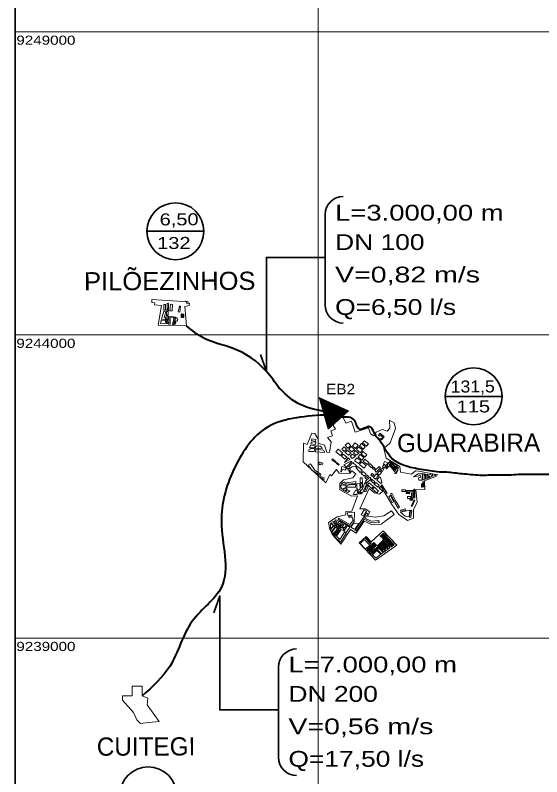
# Model space of a CAD drawing. Extents: x 0 to 1772, y 0 to 1188.
# Drawn here: x 487.8 to 598.6, y 161 to 321.1 of the extents above; entities that cross this region are included whole.
import ezdxf
from ezdxf.enums import TextEntityAlignment as Align

# ---------------------------------------------------------------- set-up
doc = ezdxf.new("R2010")
doc.units = 0
doc.header["$LTSCALE"] = 1.3
doc.linetypes.add('DOT_DASHED', pattern=[7.7, 5, -1.2, 0.3, -1.2])
doc.linetypes.add('LONG_DASHED', pattern=[7.5, 6, -1.5])
for name, color, linetype, lineweight in [('1', 7, 'DOT_DASHED', 13), ('4', 7, 'Continuous', 13), ('5', 7, 'LONG_DASHED', 25), ('6', 7, 'Continuous', 40), ('63', 7, 'Continuous', 25), ('8', 7, 'Continuous', 35), ('9', 7, 'Continuous', 40)]:
    doc.layers.add(name, color=color, linetype=linetype, lineweight=lineweight)

msp = doc.modelspace()

# ---------------------------------------------------------------- linework, layer by layer
at = {"layer": '1', "linetype": 'Continuous'}
for p, q in [((563.262, 232.663), (563.749, 233.457)), ((553.151, 222.824), (553.985, 224.573)), ((555.553, 213.259), (555.221, 213.471))]:
    msp.add_line(p, q, dxfattribs=at)
for points in [[(523.656, 261.085), (524.279, 260.753), (523.858, 260.69), (523.892, 260.461), (524.458, 260.546), (524.38, 260.047), (523.476, 259.846), (523.848, 255.792), (517.883, 255.948), (518.577, 260.092), (517.126, 260.187), (517.157, 260.657), (516.544, 260.697), (516.584, 261.31), (524.165, 260.814)], [(563.262, 232.663), (562.545, 233.076), (562.126, 234.357), (559.295, 233.433), (558.546, 235.728), (557.358, 235.34), (555.556, 239.053), (554.403, 238.494), (554.722, 237.837), (553.371, 237.181), (555.216, 234.062), (554.179, 233.705), (554.536, 232.668), (553.499, 232.311), (554.274, 231.406), (553.905, 229.172), (553.336, 229.266), (552.907, 230.716), (551.581, 231.155), (551.578, 231.995), (550.846, 233.164), (550.183, 233.251), (549.263, 230.838), (548.474, 231.139), (548.412, 227.232), (553.151, 222.824)], [(576.701, 224.479), (576.701, 224.479), (572.667, 225.222), (572.046, 225.336), (571.199, 224.614), (568.899, 225.022), (568.707, 226.266), (565.838, 227.955), (565.342, 229.991), (566.658, 231.24), (567.817, 234.223), (567.55, 235.392), (566.531, 235.955), (566.611, 234.258), (566.085, 233.652), (565.029, 233.989), (563.749, 233.457)], [(553.985, 224.573), (554.384, 224.265), (555.429, 225.615), (555.994, 224.822), (558.203, 224.763), (558.621, 225.317), (559.439, 224.699), (558.822, 223.881), (556.882, 223.41), (556.089, 222.634), (556.137, 221.307), (558.659, 220.011), (559.829, 220.036), (558.602, 216.871), (557.343, 216.779), (557.393, 216.095), (555.554, 215.637), (553.751, 214.454), (554.014, 212.962), (554.387, 212.123), (554.933, 211.445), (555.991, 210.318), (556.349, 209.938), (558.355, 212.972), (559.528, 212.196), (561.216, 214.749), (562.788, 214.025), (564.812, 214.12), (567.547, 216.166), (566.976, 216.929), (565.367, 215.87), (563.588, 215.586), (561.896, 215.793), (562.394, 216.674), (561.446, 217.351), (560.312, 217.336), (562.301, 221.63), (563.372, 220.709), (564.43, 220.422), (565.284, 221.16), (567.017, 218.225), (568.537, 216.147), (570.363, 214.89), (571.591, 215.342), (571.628, 217.105), (572.364, 218.758), (572.105, 221.347), (573.964, 221.366), (573.944, 223.225), (576.472, 224.2)], [(555.221, 213.471), (554.417, 212.355), (554.678, 212.167), (555.382, 212.861), (555.553, 213.259)]]:
    msp.add_lwpolyline(points, dxfattribs=at)
for points in [[(519.064, 259.089), (519.06, 260.291), (519.42, 260.293), (519.424, 259.09)], [(520.092, 259.451), (520.089, 260.493), (519.779, 260.492), (519.782, 259.45)], [(520.342, 258.956), (520.461, 260.345), (520.93, 260.305), (520.81, 258.916)], [(522.103, 258.751), (522.384, 259.954), (522.608, 259.902), (522.463, 258.702)], [(518.574, 257.19), (519.077, 258.878), (519.507, 258.75), (519.159, 257.584), (519.398, 257.513), (519.442, 257.081)], [(519.578, 257.144), (519.576, 257.937), (519.923, 257.938), (519.925, 257.145)], [(519.65, 258.136), (519.648, 258.793), (519.97, 258.794), (519.972, 258.137)], [(519.722, 258.979), (519.721, 259.202), (520.068, 259.203), (520.069, 258.98)], [(520.152, 256.104), (520.146, 257.852), (521.089, 257.694), (521.053, 257.477), (520.437, 257.58), (520.424, 256.117)], [(522.702, 257.55), (522.699, 258.294), (522.972, 258.294), (522.974, 257.55)], [(523.123, 257.526), (523.121, 258.27), (523.319, 258.271), (523.322, 257.527)], [(518.427, 256.508), (518.55, 256.967), (519.443, 256.895), (519.386, 256.196), (518.372, 256.278)], [(519.643, 256.276), (519.641, 256.908), (519.889, 256.909), (519.891, 256.277)], [(520.908, 256.106), (521.288, 257.645), (521.51, 257.59), (521.13, 256.051)], [(521.268, 256.07), (521.44, 256.641), (521.573, 256.6), (521.434, 256.137)], [(521.414, 256.839), (521.635, 257.571), (521.861, 257.503), (521.793, 257.277), (522.019, 257.209), (521.898, 256.807), (521.662, 256.878), (521.591, 256.643)], [(565.44, 232.496), (564.557, 233.215), (564.243, 232.829), (564.516, 232.607), (564.738, 232.88), (565.134, 232.322), (564.744, 232.045), (564.507, 232.133), (564.615, 231.906), (564.868, 231.813)], [(550.787, 230.171), (549.75, 230.168), (549.948, 230.707), (550.886, 230.61)], [(549.972, 230.995), (550.146, 231.446), (551.034, 231.323), (550.971, 230.866)], [(551.008, 231.473), (550.145, 231.671), (550.238, 232.075), (551.082, 231.882)], [(552.413, 229.951), (551.012, 230.11), (551.065, 230.578), (551.994, 230.473), (552.324, 230.239)], [(557.771, 230.075), (557.252, 230.697), (557.875, 231.216), (558.393, 230.594)], [(559.397, 230.004), (558.757, 230.595), (559.349, 231.235), (559.989, 230.644)], [(561.07, 229.887), (560.262, 230.554), (560.66, 231.035), (561.467, 230.368)], [(561.721, 230.513), (560.899, 231.18), (561.282, 231.653), (562.105, 230.986)], [(550.74, 229.358), (549.565, 229.354), (549.563, 229.73), (550.063, 230.044), (550.825, 229.959)], [(551.015, 229.309), (552.94, 229.152), (552.676, 229.689), (551.025, 229.872)], [(556.21, 228.549), (555.296, 229.322), (555.754, 229.863), (556.668, 229.09)], [(557.013, 229.373), (556.495, 229.873), (556.995, 230.392), (557.514, 229.891)], [(557.912, 228.599), (557.257, 229.176), (557.709, 229.689), (558.439, 229.047)], [(558.655, 229.317), (557.984, 229.908), (558.459, 230.446), (559.193, 229.799)], [(559.569, 228.589), (558.959, 229.12), (559.36, 229.579), (560.074, 228.957)], [(560.418, 229.124), (559.58, 229.791), (560.042, 230.371), (560.88, 229.704)], [(561.364, 228.184), (560.571, 228.912), (561.024, 229.405), (561.817, 228.677)], [(555.296, 227.269), (554.544, 227.83), (554.414, 227.656), (555.165, 227.095)], [(557.17, 227.745), (556.438, 228.397), (556.824, 228.83), (557.555, 228.177)], [(558.615, 227.278), (557.54, 226.072), (556.957, 226.592), (558.417, 227.353)], [(558.234, 227.687), (557.838, 228.021), (557.059, 227.096)], [(558.72, 227.917), (558.262, 228.387), (558.733, 228.845), (559.372, 228.436)], [(560, 226.871), (559.223, 227.416), (559.674, 228.058), (560.567, 227.431)], [(560.727, 227.588), (559.935, 228.271), (560.374, 228.781), (561.167, 228.099)], [(561.855, 226.633), (560.986, 227.345), (561.348, 227.787), (562.217, 227.074)], [(568.282, 225.818), (567.429, 226.577), (566.53, 227.2), (566.645, 227.366), (567.504, 226.771), (567.791, 226.737), (568.133, 226.409), (568.054, 226.326), (568.423, 225.971)], [(552.029, 224.369), (550.201, 225.427), (549.473, 226.526), (549.913, 226.817), (550.823, 225.443), (552.141, 224.632)], [(551.923, 226.608), (551.597, 226.845), (551.834, 227.171), (552.522, 226.936), (552.436, 226.684), (552.184, 226.77)], [(555.997, 226.671), (555.496, 227.107), (555.335, 226.923), (555.837, 226.486)], [(556.326, 225.125), (556.536, 226.252), (558.255, 225.709), (558.257, 225.07), (558.075, 225.07), (558.073, 225.48), (557.83, 225.48), (557.829, 225.723), (557.313, 225.721), (557.313, 225.493), (556.629, 225.674), (556.488, 225.14)], [(558.01, 226.195), (558.874, 227.065), (559.607, 226.338), (559.409, 226.139), (558.998, 226.244), (558.679, 226.137), (558.365, 225.931), (558.244, 225.852), (558.15, 225.885)], [(560.779, 225.443), (559.804, 226.246), (559.534, 225.919), (560.4, 224.97)], [(561.188, 225.901), (560.213, 226.643), (560.64, 227.203), (561.615, 226.46)], [(562.799, 225.951), (562.159, 226.543), (562.432, 226.838), (563.072, 226.247)], [(563.271, 225.572), (562.997, 225.815), (563.24, 226.089), (563.514, 225.846)], [(563.744, 225.071), (563.47, 225.36), (564.389, 226.235), (564.664, 225.947)], [(565.051, 225.151), (564.579, 225.515), (565.079, 225.866), (565.26, 225.609)], [(565.422, 225.889), (565.046, 226.184), (565.34, 226.559), (565.795, 226.391)], [(565.862, 226.538), (565.306, 226.719), (565.486, 227.275), (566.282, 227.018)], [(566.295, 226.097), (565.887, 225.755), (565.782, 225.88), (566.033, 226.278)], [(568.055, 225.806), (567.236, 226.565), (566.451, 227.097), (566.006, 226.44), (566.874, 226.03), (567.705, 225.101), (567.841, 225.419), (566.486, 226.574), (566.618, 226.728), (567.92, 225.617)], [(552.745, 223.458), (552.118, 223.931), (552.117, 224.144), (552.793, 223.858)], [(561.223, 224.196), (560.614, 224.742), (561.005, 225.179), (561.614, 224.633)], [(561.605, 223.665), (561.391, 223.923), (561.939, 224.376), (562.153, 224.118)], [(563.002, 224.141), (562.621, 224.414), (562.894, 224.794), (563.275, 224.522)], [(563.627, 223.58), (563.185, 223.913), (563.748, 224.659), (564.268, 224.267)], [(564.724, 222.685), (563.871, 223.352), (564.442, 224.083), (564.667, 223.907), (564.951, 222.96)], [(564.369, 224.434), (563.988, 224.783), (564.452, 225.29), (564.839, 224.936)], [(567.968, 224.727), (567.706, 224.726), (567.706, 224.874), (567.854, 224.874), (568.215, 225.614), (568.365, 225.54)], [(573.424, 223.349), (572.688, 223.346), (572.687, 223.877), (573.174, 223.964), (573.104, 224.356), (572.358, 224.222), (571.612, 224.089), (572.573, 224.716), (573.471, 224.676)], [(573.577, 223.382), (573.952, 223.544), (573.949, 224.68), (573.555, 224.679)], [(575.07, 223.922), (575.476, 224.12), (575.278, 224.526), (574.137, 224.654), (574.154, 223.565), (574.9, 223.882), (574.835, 224.036), (574.412, 223.856), (574.4, 224.418), (574.609, 224.423), (574.613, 224.214), (575.004, 224.222)], [(575.646, 224.186), (575.514, 224.592), (576.641, 224.504)], [(557.271, 222.422), (556.458, 222.557), (556.602, 222.716), (556.816, 222.866), (557, 222.914), (557.183, 222.961)], [(559.48, 222.656), (559.479, 223.112), (557.455, 222.817), (557.501, 222.502)], [(560.029, 221.232), (559.65, 221.632), (559.681, 222.556), (560.281, 222.68), (560.362, 221.534)], [(561.727, 222.551), (561.381, 222.862), (560.84, 221.524), (560.308, 220.988), (560.865, 220.622)], [(560.892, 222.883), (560.414, 222.881), (560.411, 223.817), (560.834, 223.818)], [(560.528, 221.757), (560.526, 222.625), (560.882, 222.627), (560.883, 222.014)], [(561.805, 222.768), (561.485, 223.117), (562.406, 223.962), (562.68, 223.664)], [(562.797, 221.629), (561.898, 222.418), (562.242, 222.811), (563.164, 222.002)], [(563.189, 222.726), (562.625, 223.196), (562.887, 223.511), (563.451, 223.041)], [(564.088, 221.922), (563.356, 222.529), (563.662, 222.898), (564.394, 222.291)], [(573.451, 221.922), (573.449, 222.618), (573.278, 222.617), (573.28, 221.922)], [(573.778, 221.989), (573.775, 223.013), (573.592, 223.012), (573.595, 221.988)], [(557.465, 221.875), (557.305, 222.26), (556.424, 222.355), (556.339, 222.15), (556.335, 221.953), (556.396, 221.743), (556.55, 221.559), (556.625, 221.47)], [(557.405, 221.695), (556.709, 221.376), (556.872, 221.188), (557.082, 221.09), (557.173, 221.048), (557.628, 221.503)], [(557.795, 220.736), (557.283, 220.99), (557.649, 221.325), (558.183, 221.126)], [(559.416, 221.898), (557.592, 221.893), (557.59, 222.26), (558.435, 222.43), (559.503, 222.433)], [(559.776, 220.341), (558.897, 220.338), (559.495, 221.353), (559.844, 221.148)], [(560.654, 220.488), (559.998, 220.486), (559.997, 220.943)], [(562.085, 222.007), (561.761, 222.284), (561.265, 220.98), (561.546, 220.873)], [(563.01, 221.463), (563.894, 220.674), (564.25, 221.073), (563.366, 221.861)], [(564.956, 221.164), (564.347, 221.725), (564.635, 222.039), (565.245, 221.477)], [(564.913, 221.218), (564.356, 221.693), (564.68, 222.073), (565.255, 221.582)], [(564.786, 222.183), (564.967, 222.366), (566.061, 220.653), (565.887, 220.541), (565.48, 221.39)], [(569.18, 220.965), (569.941, 220.967), (569.94, 221.308), (569.179, 221.306)], [(570.124, 220.941), (570.124, 221.217), (571.552, 221.221), (571.553, 220.946)], [(571.872, 219.634), (571.866, 221.498), (571.669, 221.497), (571.675, 219.634)], [(567.09, 218.662), (566.418, 219.959), (566.761, 220.137), (567.433, 218.84)], [(567.574, 218.952), (566.744, 220.485), (567.011, 220.63), (567.841, 219.097)], [(570.086, 220.758), (570.846, 220.76), (570.846, 220.589), (570.086, 220.587)], [(570.312, 219.485), (570.968, 219.487), (570.966, 219.894), (570.311, 219.892)], [(571.44, 219.318), (570.863, 219.316), (570.864, 219.133), (571.441, 219.134)], [(571.479, 219.502), (571.475, 220.722), (571.147, 220.721), (571.151, 219.501)], [(568.378, 217.498), (567.667, 218.69), (567.927, 218.846), (568.639, 217.654)], [(571.3, 217.835), (571.873, 219.188), (571.711, 219.257), (571.138, 217.903)], [(558.224, 214.049), (555.877, 215.407), (555.724, 215.142), (558.366, 213.613), (559.096, 214.529), (559.183, 216.609), (557.727, 216.486), (557.772, 215.951), (558.612, 216.022), (558.63, 215.815), (557.987, 215.76), (558.009, 215.506), (558.682, 215.563), (558.936, 214.873)], [(561.065, 215.78), (561.736, 216.856), (561.256, 217.156), (560.584, 216.081)], [(561.542, 215.53), (562.003, 216.326), (561.704, 216.499), (561.243, 215.703)], [(570.664, 215.655), (569.825, 215.81), (568.892, 216.634), (570.804, 217.046)], [(568.957, 216.818), (569.992, 217.057), (569.93, 217.325), (568.895, 217.086)], [(570.782, 215.616), (570.949, 216.994), (571.233, 216.96), (571.067, 215.581)], [(554.663, 214.105), (554.239, 214.395), (554.675, 214.688), (554.968, 214.252)], [(555.443, 214.611), (554.918, 214.609), (555.296, 215.008), (555.534, 214.982)], [(555.974, 214.069), (556.277, 214.587), (555.942, 214.782), (555.639, 214.265)], [(556.398, 213.792), (556.146, 213.977), (556.557, 214.537), (556.809, 214.352)], [(559.538, 212.662), (561.225, 215.131), (562.418, 214.512), (563.232, 214.408), (564.225, 214.59), (564.247, 214.466), (564.371, 214.489), (564.302, 214.866), (562.706, 214.708), (561.075, 215.497), (559.275, 212.754)], [(554.149, 213.375), (554.147, 214.223), (554.783, 213.814), (554.19, 213.163)], [(555.089, 213.576), (554.837, 213.734), (554.164, 212.924), (554.364, 212.514)], [(555.911, 213.062), (555.672, 213.26), (555.501, 212.796), (554.71, 211.919), (554.923, 211.726)], [(555.154, 213.815), (554.955, 214), (555.319, 214.391), (555.518, 214.206)], [(556.21, 210.32), (557.435, 212.192), (557.063, 212.435), (556.073, 210.923), (555.425, 211.616), (556.256, 212.785), (556.087, 212.904), (555.06, 211.458)], [(555.63, 214.068), (555.34, 213.656), (555.603, 213.471), (555.913, 213.912)], [(556.003, 213.234), (555.791, 213.406), (556.12, 213.813), (556.332, 213.642)], [(556.215, 213.089), (556.772, 212.746), (557.015, 213.142), (556.459, 213.485)], [(556.61, 213.647), (556.982, 213.317), (557.494, 213.893), (557.122, 214.223)], [(556.958, 212.654), (557.448, 212.338), (558.196, 213.497), (557.706, 213.814)], [(558.981, 213.097), (558.438, 213.454), (559.023, 214.348), (560.09, 214.227), (559.273, 213.032)], [(563.602, 206.56), (560.185, 210.176), (561.633, 211.544), (562.728, 210.386), (565.215, 212.736), (568.096, 209.687)], [(562.573, 210.01), (561.41, 211.158), (561.557, 211.308), (562.721, 210.159)], [(564.593, 211.585), (565.267, 212.22), (565.427, 212.05), (564.753, 211.415)], [(564.91, 211.283), (565.555, 211.976), (565.71, 211.831), (565.065, 211.139)], [(565.141, 211.054), (565.8, 211.703), (565.942, 211.558), (565.283, 210.909)], [(565.414, 210.868), (566.016, 211.431), (566.142, 211.296), (565.54, 210.734)], [(561.507, 208.836), (560.352, 210.066), (561.249, 210.908), (562.404, 209.678)], [(563.161, 209.012), (562.575, 209.596), (562.727, 209.749), (563.313, 209.165)], [(563.394, 209.265), (562.826, 209.848), (562.967, 209.986), (563.536, 209.403)], [(563.536, 209.403), (562.967, 209.986), (563.109, 210.124), (563.677, 209.541)], [(563.677, 209.541), (563.109, 210.124), (563.251, 210.263), (563.819, 209.679)], [(565.368, 210.585), (564.122, 209.402), (563.993, 209.537), (565.24, 210.72)], [(564.365, 209.214), (565.576, 210.361), (565.431, 210.513), (564.221, 209.366)], [(566.255, 208.859), (565.824, 208.552), (564.886, 209.512), (565.032, 209.655), (565.741, 208.929), (565.837, 209.023), (565.125, 209.753), (565.228, 209.854)], [(566.649, 209.239), (566.308, 208.949), (565.307, 209.991), (565.436, 210.115), (566.205, 209.315), (566.318, 209.424), (565.593, 210.178), (565.697, 210.277)], [(565.633, 210.624), (566.235, 211.187), (566.361, 211.053), (565.759, 210.49)], [(565.892, 210.409), (566.494, 210.972), (566.62, 210.838), (566.018, 210.275)], [(566.109, 210.136), (566.711, 210.699), (566.836, 210.565), (566.234, 210.002)], [(566.368, 209.893), (566.97, 210.455), (567.096, 210.321), (566.494, 209.758)], [(566.585, 209.634), (567.187, 210.197), (567.312, 210.063), (566.71, 209.5)], [(566.801, 209.39), (567.403, 209.953), (567.528, 209.819), (566.926, 209.256)], [(562.796, 207.832), (561.83, 208.819), (561.995, 208.98), (562.96, 207.993)], [(563.047, 208.085), (562.073, 209.072), (562.204, 209.202), (563.178, 208.214)], [(562.964, 208.741), (562.323, 209.361), (562.478, 209.52), (563.118, 208.901)], [(564.702, 207.783), (563.643, 206.97), (562.958, 207.634), (563.896, 208.602)], [(563.274, 208.421), (564.144, 209.198), (564.022, 209.335), (563.152, 208.558)], [(563.397, 208.284), (564.267, 209.06), (564.144, 209.198), (563.274, 208.421)], [(565.223, 208.145), (564.837, 207.865), (563.998, 208.691), (564.337, 209.035)], [(565.698, 208.435), (565.33, 208.217), (564.455, 209.106), (564.61, 209.258), (565.237, 208.621), (565.353, 208.734), (564.74, 209.356), (564.815, 209.431)], [(514.511, 178.013), (514.511, 180.074), (512.45, 180.074), (512.45, 178.013), (510.389, 178.013), (510.389, 177.123), (512.706, 174.505), (513.37, 172.993), (514.183, 172.218), (515.955, 172.403), (518.127, 172.629), (515.549, 176.165), (515.696, 177.566)]]:
    msp.add_lwpolyline(points, close=True, dxfattribs=at)
at = {"layer": '4'}
for p, q in [((551.784, 240.661), (551.813, 240.69)), ((551.809, 240.573), (551.891, 240.654)), ((551.834, 240.485), (551.968, 240.619)), ((551.859, 240.397), (552.046, 240.583)), ((551.884, 240.309), (552.123, 240.547)), ((551.909, 240.22), (552.201, 240.512)), ((551.934, 240.132), (552.278, 240.476)), ((551.959, 240.044), (552.356, 240.441)), ((551.984, 239.956), (552.433, 240.405)), ((552.009, 239.868), (552.511, 240.37)), ((552.034, 239.78), (552.588, 240.334)), ((552.059, 239.692), (552.666, 240.298)), ((552.084, 239.603), (552.743, 240.263)), ((552.109, 239.515), (552.821, 240.227)), ((552.134, 239.427), (552.899, 240.192)), ((552.159, 239.339), (552.976, 240.156)), ((552.184, 239.251), (553.054, 240.12)), ((552.209, 239.163), (553.131, 240.085)), ((552.234, 239.075), (553.209, 240.049)), ((552.259, 238.986), (553.286, 240.014)), ((552.284, 238.898), (553.364, 239.978)), ((552.309, 238.81), (553.441, 239.942)), ((552.334, 238.722), (553.519, 239.907)), ((552.359, 238.634), (553.596, 239.871)), ((552.384, 238.546), (553.674, 239.836)), ((552.409, 238.458), (553.751, 239.8)), ((552.434, 238.369), (553.829, 239.764)), ((552.459, 238.281), (553.907, 239.729)), ((552.484, 238.193), (553.984, 239.693)), ((552.509, 238.105), (554.062, 239.658)), ((552.534, 238.017), (554.139, 239.622)), ((552.559, 237.929), (554.217, 239.586)), ((552.584, 237.84), (554.294, 239.551)), ((552.609, 237.752), (554.372, 239.515)), ((552.634, 237.664), (554.449, 239.48)), ((552.659, 237.576), (554.527, 239.444)), ((552.684, 237.488), (554.604, 239.408)), ((552.709, 237.4), (554.682, 239.373)), ((552.734, 237.312), (554.759, 239.337)), ((552.759, 237.223), (554.837, 239.302)), ((552.784, 237.135), (554.915, 239.266)), ((552.809, 237.047), (554.992, 239.23)), ((552.834, 236.959), (555.07, 239.195)), ((552.859, 236.871), (555.147, 239.159)), ((552.884, 236.783), (555.225, 239.124)), ((552.909, 236.695), (555.302, 239.088)), ((552.934, 236.606), (555.38, 239.052)), ((552.959, 236.518), (555.457, 239.017)), ((552.984, 236.43), (555.535, 238.981)), ((553.009, 236.342), (555.612, 238.946)), ((553.034, 236.254), (555.69, 238.91)), ((553.059, 236.166), (555.767, 238.874)), ((553.084, 236.077), (555.845, 238.839)), ((553.109, 235.989), (555.923, 238.803)), ((553.134, 235.901), (556, 238.768)), ((553.159, 235.813), (556.078, 238.732)), ((553.184, 235.725), (556.155, 238.696)), ((553.209, 235.637), (556.233, 238.661)), ((553.234, 235.549), (556.31, 238.625)), ((553.259, 235.46), (556.388, 238.59)), ((553.284, 235.372), (556.465, 238.554)), ((553.309, 235.284), (556.543, 238.518)), ((553.334, 235.196), (556.62, 238.483)), ((553.359, 235.108), (556.698, 238.447)), ((553.384, 235.02), (556.775, 238.412)), ((553.409, 234.932), (556.853, 238.376)), ((553.434, 234.843), (556.931, 238.34)), ((553.459, 234.755), (557.008, 238.305)), ((553.483, 234.667), (557.086, 238.269)), ((553.508, 234.579), (557.163, 238.234)), ((553.533, 234.491), (557.241, 238.198)), ((553.558, 234.403), (557.318, 238.162)), ((553.583, 234.315), (557.396, 238.127)), ((553.608, 234.226), (557.473, 238.091)), ((553.633, 234.138), (557.551, 238.056)), ((554.312, 234.703), (557.628, 238.02)), ((555.358, 235.636), (557.706, 237.984)), ((556.404, 236.57), (557.783, 237.949)), ((557.451, 237.503), (557.861, 237.913))]:
    msp.add_line(p, q, dxfattribs=at)
msp.add_lwpolyline([(553.642, 234.106), (551.771, 240.709), (557.894, 237.898)], close=True, dxfattribs=at)
at = {"layer": '6'}
for points in [[(543.328, 242.696), (540.672, 246.223), (533.674, 251.045), (527.465, 253.206), (523.848, 255.792)], [(552.592, 237.812), (547.17, 239.573), (543.221, 242.838)], [(552.808, 237.05), (540.354, 234.161), (533.764, 225.513), (531.18, 214.67), (531.18, 200.859), (525.107, 193.76), (520.326, 184.209), (514.511, 178.013)], [(577.088, 225.024), (573.188, 225.605), (569.662, 226.446), (566.926, 228.075), (564.82, 231.23), (563.294, 233.385), (562.452, 234.594), (560.347, 234.016), (559.136, 235.961), (556.393, 236.56)], [(581.43, 224.688), (578.198, 225.03), (577.088, 225.027)], [(663.116, 215.118), (661.289, 215.641), (660.048, 215.863), (659.006, 216.112), (658.198, 216.343), (657.443, 216.586), (656.666, 216.919), (655.886, 217.281), (654.984, 217.867), (654.041, 218.336), (653.166, 218.727), (652.089, 218.802), (651.323, 218.8), (650.816, 218.995), (649.955, 218.79), (648.703, 218.612), (647.936, 218.501), (646.919, 218.498), (644.822, 218.492), (642.899, 218.486), (642.369, 218.571), (641.485, 218.681), (640.779, 218.917), (640.03, 219.205), (639.595, 219.425), (639.09, 219.725), (638.675, 220.069), (637.953, 220.489), (636.859, 220.486), (636.297, 220.228), (635.43, 220.034), (634.612, 219.844), (634.04, 219.673), (633.513, 219.572), (632.948, 219.404), (632.497, 219.232), (632.149, 219.112), (631.755, 219.041), (630.728, 219.038), (630.075, 218.807), (629.545, 218.625), (628.928, 218.486), (628.236, 218.484), (627.594, 218.38), (626.998, 218.378), (626.56, 218.377), (625.754, 218.375), (625.126, 218.116), (624.667, 217.932), (624.057, 217.93), (623.457, 218.006), (622.94, 218.28), (622.082, 218.814), (620.963, 219.454), (620.033, 220.005), (618.815, 220.611), (617.658, 221.132), (616.646, 221.509), (615.533, 221.807), (614.421, 221.997), (613.585, 222.244), (612.755, 222.426), (611.785, 222.647), (610.989, 222.825), (610.092, 223.02), (609.027, 223.211), (608.625, 223.209), (608.338, 223.312), (607.773, 223.543), (606.864, 223.674), (605.805, 223.801), (604.818, 223.947), (604.167, 224.058), (603.466, 224.224), (602.757, 224.491), (601.886, 224.488), (600.366, 224.565), (598.487, 224.559), (597.737, 224.557), (593.675, 224.545), (591.66, 224.406), (588.722, 224.398), (585.098, 224.387), (583.191, 224.548), (581.41, 224.688)]]:
    msp.add_spline(points, degree=3, dxfattribs=at)
at = {"layer": '63', "lineweight": 13}
for p, q in [((551.534, 62.735), (551.534, 419.523)), ((1175.913, 317.583), (487.822, 317.583)), ((1175.913, 253.871), (487.822, 253.871)), ((1175.913, 190.159), (487.822, 190.159))]:
    msp.add_line(p, q, dxfattribs=at)
at = {"layer": '63', "lineweight": 35}
msp.add_lwpolyline([(1175.913, 62.735), (487.822, 62.735), (487.822, 419.523)], dxfattribs=at)
at = {"layer": '8'}
for p, q in [((553.014, 260.206), (553.014, 279.162)), ((543.201, 165.112), (543.201, 184.068))]:
    msp.add_line(p, q, dxfattribs=at)
for points in [[(553.014, 270.163), (540.665, 270.163), (540.665, 246.202), (539.398, 249.768)], [(543.201, 175.069), (530.852, 175.069), (530.852, 199.031), (529.585, 195.464)]]:
    msp.add_lwpolyline(points, dxfattribs=at)
for centre, start, end in [((556.837, 279.162), 90, 180), ((556.837, 279.162), 90, 180), ((556.837, 279.162), 90, 180), ((556.837, 260.206), 180, 270), ((547.024, 184.068), 90, 180), ((547.024, 184.068), 90, 180), ((547.024, 184.068), 90, 180), ((547.024, 165.112), 180, 270)]:
    msp.add_arc(centre, 3.823, start, end, dxfattribs=at)
at = {"layer": '9', "lineweight": 35}
for p, q in [((515.538, 275.674), (527.508, 275.674)), ((578.269, 240.969), (590.24, 240.969))]:
    msp.add_line(p, q, dxfattribs=at)
for centre in [(521.523, 275.674), (584.254, 240.969), (515.806, 157.097)]:
    msp.add_circle(centre, 5.985, dxfattribs=at)

# ---------------------------------------------------------------- texts
at = {"layer": '5', "width": 1.1}
msp.add_text('EB2', height=2.2, rotation=0.006, dxfattribs=at).set_placement((556.252, 241.407), align=Align.CENTER)
at = {"layer": '63', "width": 1.25}
for s, p in [('9249000', (488.058, 314.88)), ('9244000', (488.058, 251.168)), ('9239000', (488.058, 187.456))]:
    msp.add_text(s, height=1.911, dxfattribs=at).set_placement(p)
at = {"layer": '8'}
for s, width, p in [('L=3.000,00 m', 1.3, (555.112, 277.914)), ('DN 100', 1.25, (555.112, 271.735)), ('V=0,82 m/s', 1.35, (555.112, 264.911)), ('Q=6,50 l/s', 1.25, (555.112, 258.088)), ('L=7.000,00 m', 1.3, (545.299, 182.955)), ('DN 200', 1.25, (545.299, 176.775)), ('V=0,56 m/s', 1.35, (545.299, 169.951)), ('Q=17,50 l/s', 1.25, (545.299, 163.128))]:
    msp.add_text(s, height=3.319, dxfattribs=dict(at, width=width)).set_placement(p)
at = {"layer": '9'}
for s, width, p in [('6,50 ', 1.25, (522.884, 276.92)), ('132', 1.25, (521.193, 271.947)), ('131,5', 1.1, (584.07, 241.789)), ('115', 1.25, (584.19, 237.586))]:
    msp.add_text(s, height=2.52, rotation=0.17, dxfattribs=dict(at, width=width)).set_placement(p, align=Align.CENTER)
at = {"layer": '9', "width": 1.05}
msp.add_text('PILÕEZINHOS', height=3.819, rotation=0.17, dxfattribs=at).set_placement((502.305, 263.253))
at = {"layer": '9'}
for s, p in [('GUARABIRA', (568.14, 229.269)), ('CUITEGI', (504.985, 165.444))]:
    msp.add_text(s, height=3.823, rotation=0.17, dxfattribs=at).set_placement(p)

doc.saveas('drawing.dxf')
